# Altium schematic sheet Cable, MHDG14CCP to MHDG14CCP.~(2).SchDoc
size B; Organization: Monterey Bay Aquarium Research Institute; Address1: 7700 Sandholdt Rd; Address2: Moss Landing, CA 95039-9644; CompanyName: MBARI
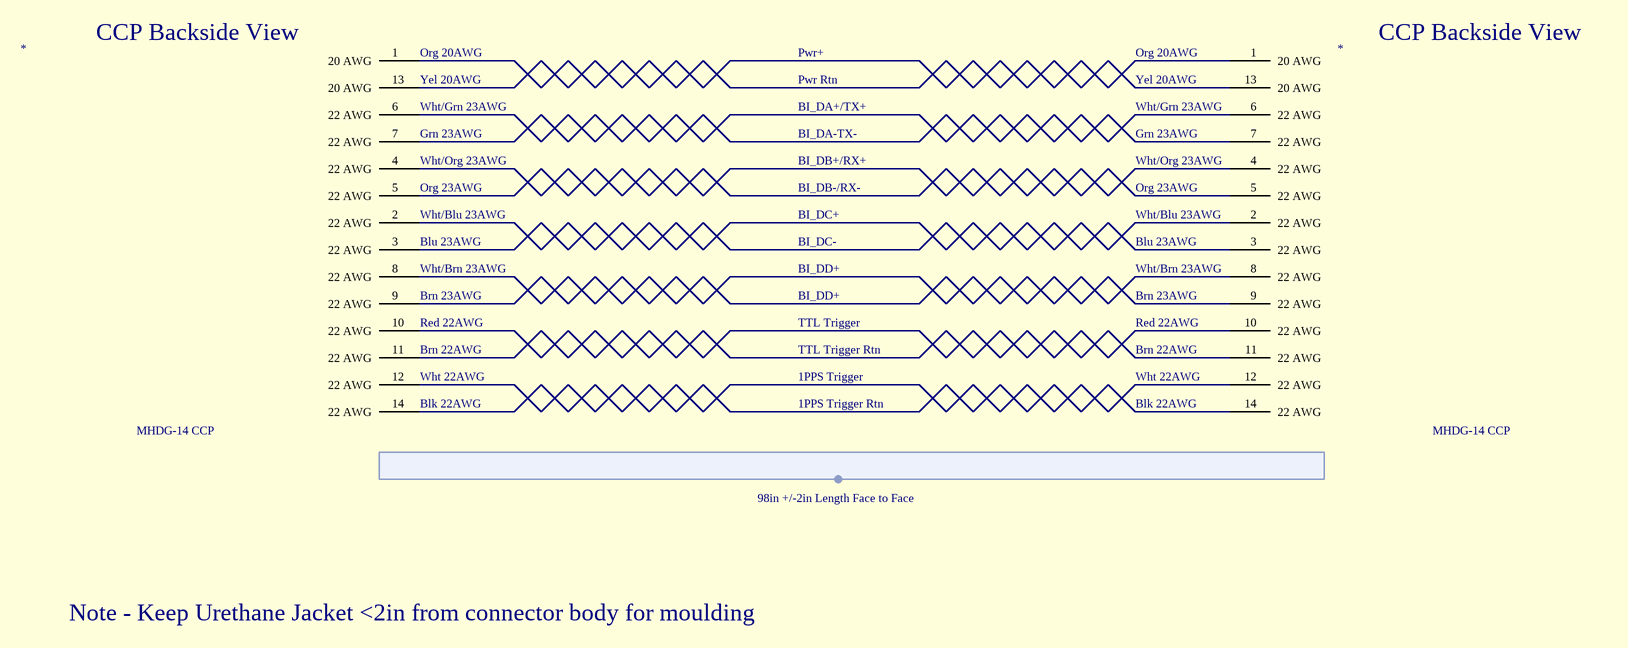
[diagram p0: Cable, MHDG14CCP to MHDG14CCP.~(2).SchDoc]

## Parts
(Parts that share a designator on the sheet are numbered #1, #2 ... from top to bottom, then left to right.)
*#1  MHDG-14 CCP
*#2  MHDG-14 CCP

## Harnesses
98in +/-2in Length Face to Face: 

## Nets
Net*#1_1: *#1.1(20_AWG) *#2.1(20_AWG)
Net*#1_2: *#1.2(22_AWG) *#2.2(22_AWG)
Net*#1_3: *#1.3(22_AWG) *#2.3(22_AWG)
Net*#1_4: *#1.4(22_AWG) *#2.4(22_AWG)
Net*#1_5: *#1.5(22_AWG) *#2.5(22_AWG)
Net*#1_6: *#1.6(22_AWG) *#2.6(22_AWG)
Net*#1_7: *#1.7(22_AWG) *#2.7(22_AWG)
Net*#1_8: *#1.8(22_AWG) *#2.8(22_AWG)
Net*#1_9: *#1.9(22_AWG) *#2.9(22_AWG)
Net*#1_10: *#1.10(22_AWG) *#2.10(22_AWG)
Net*#1_11: *#1.11(22_AWG) *#2.11(22_AWG)
Net*#1_12: *#1.12(22_AWG) *#2.12(22_AWG)
Net*#1_13: *#1.13(20_AWG) *#2.13(20_AWG)
Net*#1_14: *#1.14(22_AWG) *#2.14(22_AWG)

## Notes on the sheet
- CCP Backside View
- (near *#1) Org 20AWG
- (near *#1) Yel 20AWG
- (near *#1) Wht/Grn 23AWG
- Pwr+
- Pwr Rtn
- BI_DA+/TX+
- Org 20AWG
- Yel 20AWG
- Wht/Grn 23AWG
- (near *#1) Grn 23AWG
- (near *#1) Wht/Org 23AWG
- BI_DA-TX-
- BI_DB+/RX+
- Grn 23AWG
- Wht/Org 23AWG
- (near *#1) Org 23AWG
- (near *#1) Wht/Blu 23AWG
- (near *#1) Blu 23AWG
- BI_DB-/RX-
- BI_DC+
- BI_DC-
- Org 23AWG
- Wht/Blu 23AWG
- Blu 23AWG
- (near *#1) Wht/Brn 23AWG
- (near *#1) Brn 23AWG
- BI_DD+
- Wht/Brn 23AWG
- Brn 23AWG
- (near *#1) Red 22AWG
- (near *#1) Brn 22AWG
- (near *#1) Wht 22AWG
- TTL Trigger
- TTL Trigger Rtn
- 1PPS Trigger
- Red 22AWG
- Brn 22AWG
- Wht 22AWG
- (near *#1) Blk 22AWG
- 1PPS Trigger Rtn
- Blk 22AWG
- Note - Keep Urethane Jacket <2in from connector body for moulding

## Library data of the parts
*#1 *#2 = MHDG-14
